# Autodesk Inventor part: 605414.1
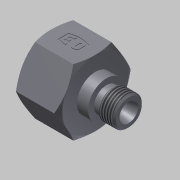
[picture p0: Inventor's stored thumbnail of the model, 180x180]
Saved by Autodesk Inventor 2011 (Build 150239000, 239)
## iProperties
Created: 2014-02
Part Number: 605414.1
Document SubType Name: Modeling
Designer: dorohin
Density: 7.85 g/cm^3
Mass: 193.984 g
Surface Area: 93.6865 cm^2
Volume: 24.7113 cm^3
Material: Сталь
Стандарт преобразования: STEP AP203
Имя файла: C:/Users/dorohin/Documents/EO Tube end reducer - Steel and Brass KOR20_08SOMDCF.stp
Постпроцессор: Build: 309, Release: 2011 SP2 - Date: Thu 04/28/2011
Отправленные единицы: миллиметр
Неопределенность: 1.0000000000000002e-06
Author: dorohin
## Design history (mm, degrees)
feature "БазТело1"
feature "Резьба1" dims "d0" = 10, "d1" = 0
feature "Резьба2" dims "d2" = 10, "d3" = 0
node "1"
